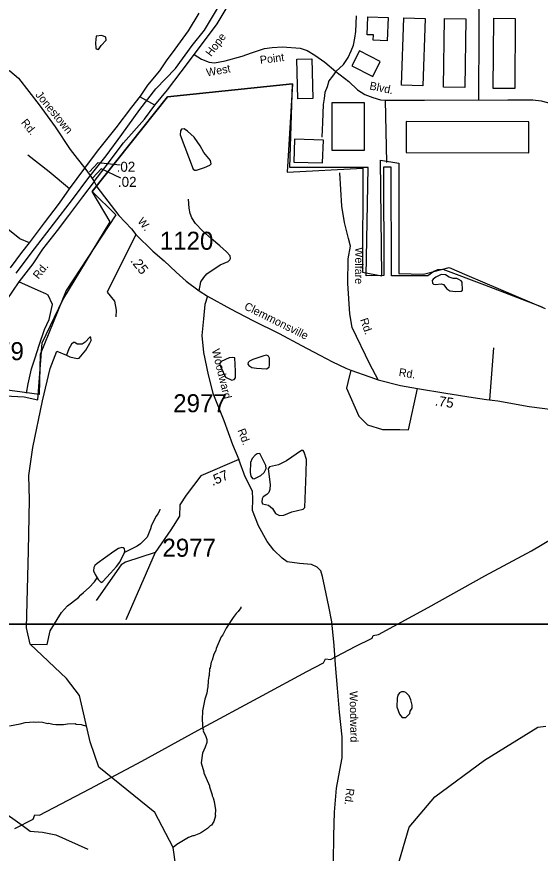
# Model space of a CAD drawing. Extents: x 1551653 to 1702041, y 811336 to 920032.
# Drawn here: x 1605321 to 1609613, y 829431 to 836287 of the extents above; entities that cross this region are included whole.
import ezdxf

# ---------------------------------------------------------------- set-up
doc = ezdxf.new("R2010")
doc.units = 0
for name, color, linetype in [('Old_Level_10', 7, 'Continuous'), ('Old_Level_11', 7, 'Continuous'), ('Old_Level_17', 7, 'Continuous'), ('Old_Level_28', 7, 'Continuous'), ('Old_Level_32', 7, 'Continuous'), ('Old_Level_35', 7, 'Continuous'), ('Old_Level_41', 7, 'Continuous'), ('Old_Level_44', 7, 'Continuous'), ('Old_Level_48', 7, 'Continuous'), ('Old_Level_49', 7, 'Continuous'), ('Old_Level_56', 7, 'Continuous'), ('Old_Level_59', 7, 'Continuous'), ('Old_Level_62', 7, 'Continuous'), ('Old_Level_63', 7, 'Continuous'), ('Old_Level_8', 7, 'Continuous')]:
    doc.layers.add(name, color=color, linetype=linetype)

msp = doc.modelspace()

# ---------------------------------------------------------------- linework, layer by layer
at = {"layer": 'Old_Level_17'}
for points in [[(1606168.465, 835069.489), (1605986.512, 835088.909), (1605918.154, 835014.723)], [(1606174.722, 834962.843), (1606014.458, 835039.63), (1605946.1, 834965.443)]]:
    msp.add_lwpolyline(points, dxfattribs=at)
at = {"layer": 'Old_Level_28'}
for points in [[(1605879.846, 835046.35), (1605982.203, 835183.915), (1606135.738, 835374.786), (1606263.683, 835544.708), (1606335.797, 835635.488), (1606395.352, 835724.871), (1606493.055, 835843.583), (1606548.885, 835925.053), (1606618.838, 836021.636), (1606728.936, 836170.539), (1606817.794, 836315.607)], [(1605270.826, 834229.795), (1605363.877, 834355.491), (1605426.687, 834432.305), (1605549.515, 834597.104), (1605672.808, 834757.716), (1605754.227, 834876.428), (1605879.846, 835046.35)]]:
    msp.add_lwpolyline(points, dxfattribs=at)
at = {"layer": 'Old_Level_32'}
for p, q in [((1605879.846, 835046.35), (1605924.541, 834984.153)), ((1605924.541, 834984.153), (1605954.761, 834935.405))]:
    msp.add_line(p, q, dxfattribs=at)
for points in [[(1605954.761, 834935.405), (1605859.771, 834809.254), (1605745.513, 834658.001), (1605653.708, 834534.49), (1605533.145, 834380.916), (1605453.427, 834260.752), (1605338, 834115.062), (1605128.566, 833808.138)], [(1605954.761, 834935.405), (1605978.864, 834892.832), (1606159.118, 834658.326), (1606261.516, 834546.988), (1606296.426, 834502.604), (1606435.734, 834366.153), (1606530.4, 834286.058), (1606627.161, 834192.843), (1606710.127, 834119.92), (1606816.974, 834040.511), (1606884.744, 833997.022)], [(1606884.744, 833997.022), (1606862.199, 833927.071), (1606853.181, 833811.991), (1606837.4, 833674.346), (1606853.181, 833534.444), (1606891.509, 833351.67), (1606929.835, 833202.743), (1607019.639, 832978.451), (1607089.53, 832782.137), (1607140.957, 832657.354), (1606831.136, 832523.837), (1606710.43, 832365.856), (1606659.363, 832286.866), (1606654.72, 832193.937), (1606585.083, 832082.421), (1606455.092, 831896.561), (1606214.71, 831343.207)], [(1606884.744, 833997.022), (1607074.729, 833893.402), (1607257.272, 833797.047), (1607471.625, 833690.443), (1607656.316, 833591.44), (1607806.791, 833512.346), (1607909.967, 833459.026), (1608019.183, 833407.582), (1608061.515, 833389.653), (1608216.02, 833335.151), (1608283.761, 833311.524), (1608467.073, 833263.998), (1608608.027, 833239.992), (1608838.951, 833200.981), (1609063.878, 833164.97), (1609171.843, 833149.966), (1609264.812, 833137.963), (1609522.728, 833092.95), (1609798.638, 833056.94), (1610125.531, 833005.926), (1610377.448, 832966.915), (1610563.388, 832936.907), (1610647.36, 832924.903)]]:
    msp.add_lwpolyline(points, dxfattribs=at)
at = {"layer": 'Old_Level_35'}
for p, q in [((1606453.028, 835561.942), (1606558.608, 835686.469)), ((1606453.028, 835561.942), (1606331.187, 835629.684)), ((1608342.029, 835601.85), (1608351.644, 835091.933)), ((1606296.426, 834502.604), (1606062.27, 834027.994)), ((1609200.33, 833146.289), (1609232.291, 833573.541))]:
    msp.add_line(p, q, dxfattribs=at)
for points in [[(1609465.121, 837833.929), (1609415.37, 837781.037), (1609333.193, 837673.926), (1609255.985, 837567.033), (1609175.338, 837469.516), (1609136.685, 837389.399), (1609106.315, 837281.658), (1609100.793, 837093.801), (1609106.438, 836929.557), (1609111.245, 836756.378), (1609106.43, 835604.967)], [(1606558.608, 835686.469), (1606668.483, 835835.123), (1606843.273, 836066.711), (1606963.191, 836227.17), (1607079.552, 836419.519), (1607177.223, 836606.63), (1607215.521, 836700.96), (1607244.982, 836795.29), (1607286.226, 836939.732), (1607300.955, 837066.488), (1607324.524, 837234.513), (1607335.309, 837347.65)], [(1607938.19, 835837.566), (1608000.689, 835895.292), (1608039.15, 835953.019), (1608063.188, 836005.935), (1608082.418, 836054.04), (1608092.034, 836111.767), (1608101.649, 836164.682), (1608106.456, 836294.566)], [(1606774.75, 835977.072), (1606837.249, 835938.588), (1606899.748, 835914.534), (1606943.016, 835909.724), (1607029.553, 835924.155), (1607168.974, 835962.64), (1607245.895, 835991.504), (1607303.586, 836010.746), (1607351.663, 836025.177), (1607414.161, 836034.798), (1607500.698, 836039.609), (1607644.927, 836029.988), (1607702.618, 836010.746), (1607765.117, 835972.261), (1607846.845, 835914.534), (1607938.19, 835837.566)], [(1605202.614, 835877.635), (1605265.584, 835843.505), (1605336.426, 835783.122), (1605504.346, 835563.905), (1605635.533, 835385.381), (1605759.299, 835199.003), (1605816.215, 835124.406), (1605879.846, 835046.35)], [(1607938.19, 835837.566), (1607909.345, 835799.082), (1607880.499, 835760.598), (1607866.076, 835712.492), (1607846.845, 835664.387), (1607842.038, 835616.282), (1607832.423, 835568.176), (1607827.615, 835419.05), (1607822.808, 835298.787)], [(1607938.19, 835837.566), (1608043.957, 835755.787), (1608116.071, 835688.44), (1608173.762, 835649.956), (1608241.069, 835625.903), (1608303.568, 835606.661), (1608342.029, 835601.85)], [(1608342.029, 835601.85), (1608664.138, 835601.85), (1609346.818, 835606.661), (1609491.046, 835606.661), (1609553.545, 835606.661), (1609620.851, 835597.04), (1609673.735, 835582.608), (1609750.656, 835558.555), (1609861.231, 835510.45), (1609938.153, 835481.587), (1610005.46, 835452.723), (1610043.92, 835438.292), (1610337.184, 835433.481)], [(1605954.761, 834935.405), (1606046.096, 835054.242), (1606195.888, 835251.695), (1606369.655, 835447.165), (1606453.028, 835561.942)], [(1605754.227, 834876.428), (1605587.275, 835014.987), (1605413.345, 835151.191)], [(1608283.761, 833311.524), (1608215.589, 833439.075), (1608070.353, 833738.673), (1608052.569, 833851.393), (1608034.786, 834100.564), (1608037.749, 834302.274), (1608058.517, 834407.379), (1608040.732, 834469.673), (1608008.128, 834600.19), (1607987.38, 834733.675), (1607969.596, 835006.576)], [(1605426.687, 834432.305), (1605347.594, 834467.22), (1605147.533, 834625.503), (1605021.914, 834723.266), (1604919.93, 834847.822)], [(1606816.974, 834040.511), (1606831.869, 834113.851), (1606853.805, 834149.625), (1606880.622, 834179.297), (1606989.388, 834253.732), (1607053.778, 834281.042), (1607067.862, 834294.766), (1607074.067, 834304.644), (1607070.313, 834326.734), (1607040.753, 834359.152), (1606987.554, 834409.857), (1606918.27, 834466.694), (1606845.347, 834531.609), (1606788.145, 834592.203), (1606756.669, 834638.666), (1606743.194, 834674.762), (1606733.88, 834718.774), (1606730.744, 834790.877)], [(1605401.596, 833201.136), (1605414.539, 833276.917), (1605442.259, 833400.424), (1605471.334, 833492.084), (1605506.058, 833594.004), (1605549.9, 833721.984), (1605588.26, 833804.256), (1605613.834, 833928.578), (1605579.072, 834005.699), (1605560.859, 834014.507), (1605496.925, 834041.931), (1605338, 834115.062)], [(1606062.27, 834027.994), (1606121.55, 833956.802), (1606136.37, 833882.644), (1606133.406, 833826.284)], [(1608061.515, 833389.653), (1608034.84, 833288.797), (1608025.948, 833241.337)], [(1608025.948, 833241.337), (1608126.724, 833012.93), (1608197.859, 832941.738), (1608319.383, 832903.176), (1608461.655, 832903.176), (1608532.791, 832900.21), (1608608.027, 833239.992)], [(1607916.984, 829361.131), (1607920.373, 829573.058), (1607927.15, 829766.335), (1607944.094, 829963.003), (1607971.205, 830112.199), (1607988.149, 830213.924), (1607988.149, 830386.178), (1607967.816, 830586.237), (1607950.872, 830782.905), (1607933.928, 830976.182), (1607923.761, 831132.16), (1607903.429, 831328.15), (1607879.708, 831453.611), (1607845.82, 831609.588), (1607828.876, 831697.75), (1607815.321, 831745.222), (1607784.822, 831775.739), (1607737.38, 831796.084), (1607639.106, 831806.256), (1607537.442, 831819.82), (1607497.501, 831849.088), (1607428.419, 831915.925), (1607375.424, 831986.637), (1607303.618, 832114.822), (1607252.787, 832240.282), (1607256.175, 832331.835), (1607252.787, 832399.651), (1607195.178, 832514.94), (1607140.957, 832657.354)], [(1606455.092, 831896.561), (1606213.682, 831817.571), (1606176.542, 831794.338), (1605972.272, 831501.61)], [(1603013.068, 829774.862), (1603072.325, 829797.103), (1603242.69, 829785.983), (1603998.223, 829745.207), (1604368.581, 829734.086), (1604487.097, 829734.086), (1604550.057, 829711.845), (1604653.758, 829700.724), (1604783.384, 829730.379), (1604898.195, 829819.345), (1604987.081, 829889.776), (1605031.524, 829893.483), (1605098.189, 829863.828), (1605183.371, 829789.689), (1605364.848, 829659.948), (1605431.512, 829611.758), (1605531.509, 829604.344), (1605642.616, 829582.103), (1605904.8, 829463.991)]]:
    msp.add_lwpolyline(points, dxfattribs=at)
at = {"layer": 'Old_Level_41'}
for points in [[(1608366.858, 836279.873), (1608359.368, 836088.742), (1608243.306, 836093.29), (1608245.017, 836136.954), (1608194.355, 836138.938), (1608200.133, 836286.405), (1608366.858, 836279.873)], [(1608670.196, 836272.378), (1608651.524, 835719.273), (1608475.461, 835725.217), (1608494.133, 836278.322), (1608670.196, 836272.378)], [(1609003.493, 836268.631), (1608995.972, 835707.866), (1608819.992, 835710.226), (1608827.514, 836270.991), (1609003.493, 836268.631)], [(1609407.945, 836272.378), (1609404.217, 835697.841), (1609228.189, 835698.984), (1609231.917, 836273.521), (1609407.945, 836272.378)], [(1608301.12, 835920.711), (1608130.424, 836006.122), (1608068.935, 835883.234), (1608239.631, 835797.824), (1608301.12, 835920.711)], [(1607741.456, 835942.582), (1607748.719, 835615.527), (1607625.364, 835612.787), (1607618.101, 835939.843), (1607741.456, 835942.582)], [(1608168.377, 835582.805), (1608168.377, 835189.3), (1607906.233, 835189.3), (1607906.233, 835582.805), (1608168.377, 835582.805)], [(1609520.292, 835425.403), (1608513.865, 835429.175), (1608512.91, 835174.309), (1609519.336, 835170.537), (1609520.292, 835425.403)], [(1607835.08, 835275.496), (1607597.615, 835283.04), (1607591.66, 835095.607), (1607829.125, 835088.064), (1607835.08, 835275.496)]]:
    msp.add_lwpolyline(points, dxfattribs=at)
at = {"layer": 'Old_Level_44'}
msp.add_lwpolyline([(1605315.914, 834185.625), (1605468.21, 834383.647), (1605622.787, 834585.628), (1605779.168, 834787.57), (1605913.291, 834967.75), (1606053.419, 835147.812), (1606183.579, 835320.069), (1606330.033, 835526.013), (1606462.162, 835696.429), (1606621.56, 835862.375), (1606759.847, 836050.475), (1606861.729, 836176.994), (1606965.953, 836353.584)], dxfattribs=at)
at = {"layer": 'Old_Level_48'}
msp.add_lwpolyline([(1605066.717, 833188.883), (1605382.736, 833170.95), (1605494.198, 833146.234), (1605529.506, 833613.814), (1605699.529, 833966.769), (1606086.909, 834605.667), (1605938.819, 834855.458), (1606555.936, 835630.698), (1607581.415, 835737.164), (1607537.336, 835012.345), (1608158.53, 835046.328), (1608156.987, 834193.969), (1608314.729, 834163.61), (1608302.595, 835110.802), (1608454.27, 835086.514), (1608454.27, 834181.825), (1608657.267, 834175.761), (1608739.613, 834199.01), (1608866.826, 834230.4), (1609012.435, 834169.682), (1609653.257, 833894.147)], dxfattribs=at)
at = {"layer": 'Old_Level_49'}
msp.add_lwpolyline([(1609628.554, 833906.552), (1609158.284, 834085.511), (1608816.131, 834214.375), (1608769.666, 834212.263), (1608739.613, 834199.01), (1608691.52, 834163.674), (1608393.72, 834163.674), (1608392.21, 835054.159), (1608328.849, 835054.159), (1608330.961, 834165.551), (1608185.229, 834163.439), (1608202.161, 835051.884), (1607559.795, 835051.171), (1607581.415, 835737.164), (1606555.936, 835630.698), (1605938.819, 834855.458), (1606132.407, 834664.186), (1605725.946, 834042.602), (1605514.443, 833517.644), (1605504.29, 833190.162), (1605365.9, 833208.444), (1605096.952, 833245.008)], dxfattribs=at)
at = {"layer": 'Old_Level_56'}
msp.add_lwpolyline([(1605306.002, 829633.276), (1605455.254, 829710.894), (1605469.746, 829744.621), (1605507.515, 829742.052), (1605920.545, 829959.6), (1606345.741, 830184.905), (1606807.354, 830439.691), (1607335.388, 830723.342), (1607700.164, 830919.658), (1607837.093, 830991.521), (1607851.585, 831025.248), (1607893.474, 831018.594), (1608094.947, 831125.369), (1608233.795, 831193.19), (1608242.243, 831215.034), (1608288.218, 831222.505), (1608693.368, 831446.015), (1609159.062, 831704.718), (1609542.044, 831910.669), (1609717.391, 832011.972)], dxfattribs=at)
at = {"layer": 'Old_Level_59'}
for points in [[(1606665.69, 828095.817), (1606688.324, 828230.787), (1606797.712, 828365.092), (1606953.003, 828719.847), (1606769.764, 828959.283), (1606648.69, 829167.521), (1606603.579, 829478.123), (1606453.304, 829765.921), (1605994.676, 830135.982), (1605922.703, 830344.315), (1605835.659, 830723.559), (1605729.647, 830863.609), (1605432.629, 831145.351), (1605401.666, 831277.302), (1605418.685, 831910.503), (1605426.909, 832328.203), (1605421.818, 832526.884), (1605452.359, 832756.13), (1605533.798, 833138.209), (1605594.877, 833403.116), (1605650.867, 833545.759), (1605728.929, 833511.805)], [(1606665.69, 828095.817), (1606891.923, 828225.693), (1607162.653, 828310.198), (1607833.566, 828602.676), (1608128.785, 828653.62), (1608244.337, 828846.102), (1608341.046, 828973.461), (1608539.466, 829644.02), (1608748.154, 829893.644), (1609155.657, 830193.397), (1609592.725, 830463.604), (1609659.675, 830472.113)]]:
    msp.add_lwpolyline(points, dxfattribs=at)
at = {"layer": 'Old_Level_62'}
for points in [[(1606013.029, 836050.299), (1606054.962, 836095.257), (1606051.681, 836119.145), (1606020.103, 836132.218), (1605973.351, 836128.527), (1605966.892, 836071.727), (1605969.353, 836028.871), (1605979.4, 836020.618), (1605992.421, 836019.131), (1606013.029, 836050.299)], [(1606859.732, 835052.003), (1606905.151, 835068.92), (1606915.506, 835081.326), (1606910.38, 835107.675), (1606855.016, 835174.522), (1606825.181, 835227.938), (1606777.096, 835300.116), (1606722.142, 835349.636), (1606692.615, 835367.886), (1606671.084, 835364.554), (1606663.19, 835352.097), (1606661.037, 835318.109), (1606767.664, 835036.47), (1606780.685, 835028.576), (1606796.166, 835028.371), (1606859.732, 835052.003)], [(1608897.804, 834141.572), (1608866.841, 834150.85), (1608837.621, 834172.586), (1608800.404, 834173.406), (1608756.625, 834152.081), (1608734.993, 834135.779), (1608727.611, 834124.501), (1608728.636, 834103.073), (1608736.633, 834095.333), (1608754.678, 834091.488), (1608799.584, 834096.614), (1608821.012, 834092.77), (1608846.848, 834055.296), (1608872.89, 834040.02), (1608920.462, 834034.637), (1608965.779, 834037.354), (1608975.519, 834046.941), (1608973.058, 834110.814), (1608963.831, 834123.066), (1608945.376, 834134.19), (1608928.869, 834140.444), (1608897.804, 834141.572)], [(1605861.598, 833520.725), (1605889.075, 833554.61), (1605920.96, 833610.948), (1605930.803, 833634.222), (1605929.777, 833660.93), (1605919.73, 833659.802), (1605881.385, 833620.175), (1605857.497, 833603.771), (1605816.999, 833602.131), (1605798.442, 833617.356), (1605787.984, 833616.639), (1605769.119, 833601.823), (1605749.537, 833565.786), (1605728.929, 833511.805), (1605756.303, 833499.4), (1605817.409, 833485.764), (1605832.07, 833487.712), (1605861.598, 833520.725)], [(1606994.669, 833415.649), (1607033.936, 833332.295), (1607085.097, 833307.843), (1607103.961, 833312.661), (1607114.829, 833326.964), (1607116.06, 833381.61), (1607108.473, 833490.339), (1607090.941, 833494.953), (1607062.643, 833491.467), (1606997.642, 833460.811), (1606987.492, 833447.74), (1606985.441, 833435.232), (1606994.669, 833415.649)], [(1607346.502, 833508.506), (1607257.099, 833478.721), (1607229.93, 833463.958), (1607219.165, 833451.552), (1607216.499, 833438.378), (1607223.881, 833426.998), (1607249.512, 833412.9), (1607287.652, 833405.57), (1607369.878, 833401.469), (1607389.46, 833413.823), (1607394.074, 833431.97), (1607393.356, 833489.128), (1607386.077, 833504.917), (1607369.775, 833512.658), (1607346.502, 833508.506)], [(1607251.671, 832665.607), (1607238.035, 832634.285), (1607235.575, 832550.111), (1607241.726, 832521.609), (1607252.901, 832501.36), (1607268.383, 832498.951), (1607323.644, 832525.967), (1607349.276, 832550.368), (1607365.578, 832582.766), (1607363.219, 832609.73), (1607313.904, 832705.848), (1607293.399, 832704.208), (1607275.457, 832693.802), (1607251.671, 832665.607)], [(1607531.939, 832648.166), (1607467.86, 832613.615), (1607392.298, 832598.544), (1607383.686, 832581.883), (1607398.245, 832451.675), (1607395.272, 832411.434), (1607386.659, 832388.058), (1607371.383, 832370.628), (1607341.753, 832350.841), (1607332.423, 832334.18), (1607330.475, 832309.83), (1607336.934, 832293.836), (1607386.352, 832284.916), (1607417.93, 832256.004), (1607441.716, 832215.506), (1607475.139, 832200.025), (1607510.306, 832202.946), (1607577.665, 832229.04), (1607668.503, 832249.853), (1607682.037, 832263.129), (1607695.16, 832548.152), (1607695.57, 832658.88), (1607678.551, 832717.781), (1607669.529, 832730.443), (1607654.457, 832731.468), (1607531.939, 832648.166)], [(1606494.696, 832251.76), (1606490.492, 832235.818), (1606478.189, 832212.032), (1606463.938, 832192.244), (1606427.029, 832120.732), (1606418.519, 832088.898), (1606389.709, 832021.282), (1606337.011, 831968.02), (1606308.714, 831948.437), (1606203.727, 831896.559)], [(1606203.727, 831896.559), (1606206.188, 831910.451), (1606205.573, 831925.625), (1606194.705, 831933.981), (1606181.581, 831935.57), (1606154.31, 831928.137), (1606116.58, 831905.222), (1605979.913, 831805.106), (1605960.843, 831788.343), (1605952.333, 831773.323), (1605950.59, 831745.179), (1605964.841, 831715.344), (1605981.143, 831687.816)], [(1605981.143, 831687.816), (1605989.243, 831674.231), (1606012.311, 831650.138), (1606027.895, 831657.264), (1606090.333, 831726.059), (1606139.033, 831781.935), (1606165.997, 831816.845), (1606189.168, 831861.803), (1606202.189, 831887.383), (1606203.727, 831896.559)], [(1605432.629, 831145.351), (1605570.116, 831140.942), (1605595.645, 831252.542), (1605687.611, 831403.204), (1605738.361, 831458.516), (1605827.251, 831527.261), (1605845.501, 831548.996), (1605869.8, 831566.631), (1605916.347, 831609.999), (1605958.895, 831655.366), (1605981.143, 831687.816)], [(1607159.475, 831450.674), (1607157.322, 831442.727), (1607136.919, 831410.996), (1607120.72, 831395.258), (1607096.319, 831363.577), (1607037.161, 831276.43), (1607010.402, 831220.81), (1606998.201, 831205.021), (1606956.883, 831109.62), (1606952.68, 831093.678), (1606936.276, 831061.895), (1606923.562, 831014.066), (1606915.36, 830998.226), (1606906.748, 830950.346), (1606902.647, 830942.4), (1606899.879, 830886.421), (1606895.778, 830878.527), (1606891.369, 830846.59), (1606888.601, 830790.611), (1606884.5, 830782.665), (1606879.886, 830742.731), (1606863.277, 830695.005), (1606844.002, 830599.297), (1606841.029, 830527.375), (1606847.898, 830447.251), (1606851.794, 830439.202), (1606849.744, 830433.256), (1606871.069, 830386.966), (1606878.759, 830362.872), (1606878.451, 830338.881), (1606865.84, 830299.049), (1606845.233, 830251.375), (1606834.16, 830171.507), (1606855.178, 830099.226), (1606855.075, 830091.229), (1606901.519, 829982.654), (1606901.417, 829974.657), (1606924.588, 829910.322), (1606924.383, 829902.325), (1606932.175, 829886.229), (1606939.762, 829854.138), (1606950.834, 829786.009), (1606948.271, 829746.024), (1606950.219, 829738.027), (1606937.506, 829690.199), (1606917.103, 829660.466), (1606907.056, 829654.622), (1606884.808, 829632.938), (1606828.316, 829595.721), (1606772.029, 829572.55), (1606764.032, 829572.652), (1606729.891, 829561.119), (1606633.106, 829502.474), (1606603.579, 829478.123)], [(1608553.098, 830688.083), (1608538.95, 830719.764), (1608511.37, 830749.189), (1608498.144, 830754.777), (1608475.691, 830753.187), (1608459.287, 830746.113), (1608446.266, 830725.659), (1608439.397, 830702.694), (1608436.834, 830631.181), (1608459.184, 830569.717), (1608480.715, 830544.649), (1608511.575, 830544.291), (1608542.846, 830576.689), (1608547.869, 830596.015), (1608563.248, 830621.288), (1608563.556, 830644.305), (1608553.098, 830688.083)], [(1605261.205, 830475.394), (1605349.378, 830492.158), (1605389.568, 830503.589), (1605461.541, 830508.562), (1605477.535, 830506.357), (1605501.526, 830508.049), (1605533.514, 830505.589), (1605565.297, 830497.13), (1605577.293, 830494.977), (1605585.29, 830496.874), (1605617.176, 830488.415), (1605641.167, 830486.109), (1605705.143, 830485.186), (1605737.131, 830490.773), (1605801.21, 830493.849), (1605809.104, 830489.748), (1605848.987, 830485.186), (1605892.048, 830471.601)]]:
    msp.add_lwpolyline(points, dxfattribs=at)
at = {"layer": 'Old_Level_63'}
for points in [[(1569096.749, 874749.337), (1631612.821, 874749.337), (1631612.821, 831307.151), (1569096.749, 831307.151), (1569096.749, 874749.337)], [(1577049.889, 831307.151), (1641328.558, 831307.151), (1641328.558, 811336.298), (1577049.889, 811336.298), (1577049.889, 831307.151)]]:
    msp.add_lwpolyline(points, dxfattribs=at)

# ---------------------------------------------------------------- texts
at = {"layer": 'Old_Level_10'}
for s, height, rotation, p in [('Hope', 65.6167, 53.2276944, (1606915.665, 835954.523)), ('Point', 65.6167, 7.0055833, (1607318.534, 835899.418)), ('West', 65.6166, 10.0962972, (1606880.663, 835796.703)), ('Blvd.', 65.6167, 348.2201056, (1608209.36, 835691.246)), ('Jonestown', 65.6167, 309.4999139, (1605470.485, 835644.368)), ('Rd.', 65.6167, 309.4999139, (1605352.167, 835416.271)), ('Welfare', 65.6167, 269.6789278, (1608096.177, 834397.113)), ('Rd.', 65.6167, 288.9190444, (1608135.522, 833804.393)), ('Woodward', 65.6167, 271.0271861, (1608049.755, 830759.257)), ('Rd.', 65.6167, 263.0442972, (1608024.916, 829966.278))]:
    msp.add_text(s, height=height, rotation=rotation, dxfattribs=at).set_placement(p)
at = {"layer": 'Old_Level_11'}
for s, height, rotation, p in [('W.', 65.6167, 309.689975, (1606307.456, 834607.319)), ('Rd.', 65.6167, 51.381275, (1605499.409, 834131.684)), ('Clemmonsville', 65.61666, 333.5575028, (1607180.358, 833891.682)), ('Woodward', 65.6167, 283.9357, (1606920.206, 833556.017)), ('Rd.', 65.6167, 350.6165389, (1608449.813, 833343.174)), ('Rd.', 65.6167, 290.4749472, (1607130.399, 832897.638))]:
    msp.add_text(s, height=height, rotation=rotation, dxfattribs=at).set_placement(p)
at = {"layer": 'Old_Level_17'}
for p in [(1606140.212, 835016.049), (1606150.858, 834892.183)]:
    msp.add_text('.02', height=82.0208, dxfattribs=at).set_placement(p)
for s, rotation, p in [('.25', 308.5637556, (1606248.655, 834285.226)), ('.75', 351.9014222, (1608746.539, 833100.731)), ('.57', 23.3136389, (1606926.293, 832440.083))]:
    msp.add_text(s, height=82.0208, rotation=rotation, dxfattribs=at).set_placement(p)
at = {"layer": 'Old_Level_8'}
for s, p in [('1120', (1606494.251, 834376.786)), ('2979', (1604940.795, 833471.961)), ('2977', (1606604.014, 833045.387)), ('2977', (1606515.574, 831861.074))]:
    msp.add_text(s, height=147.6375, dxfattribs=at).set_placement(p)

doc.saveas('drawing.dxf')
